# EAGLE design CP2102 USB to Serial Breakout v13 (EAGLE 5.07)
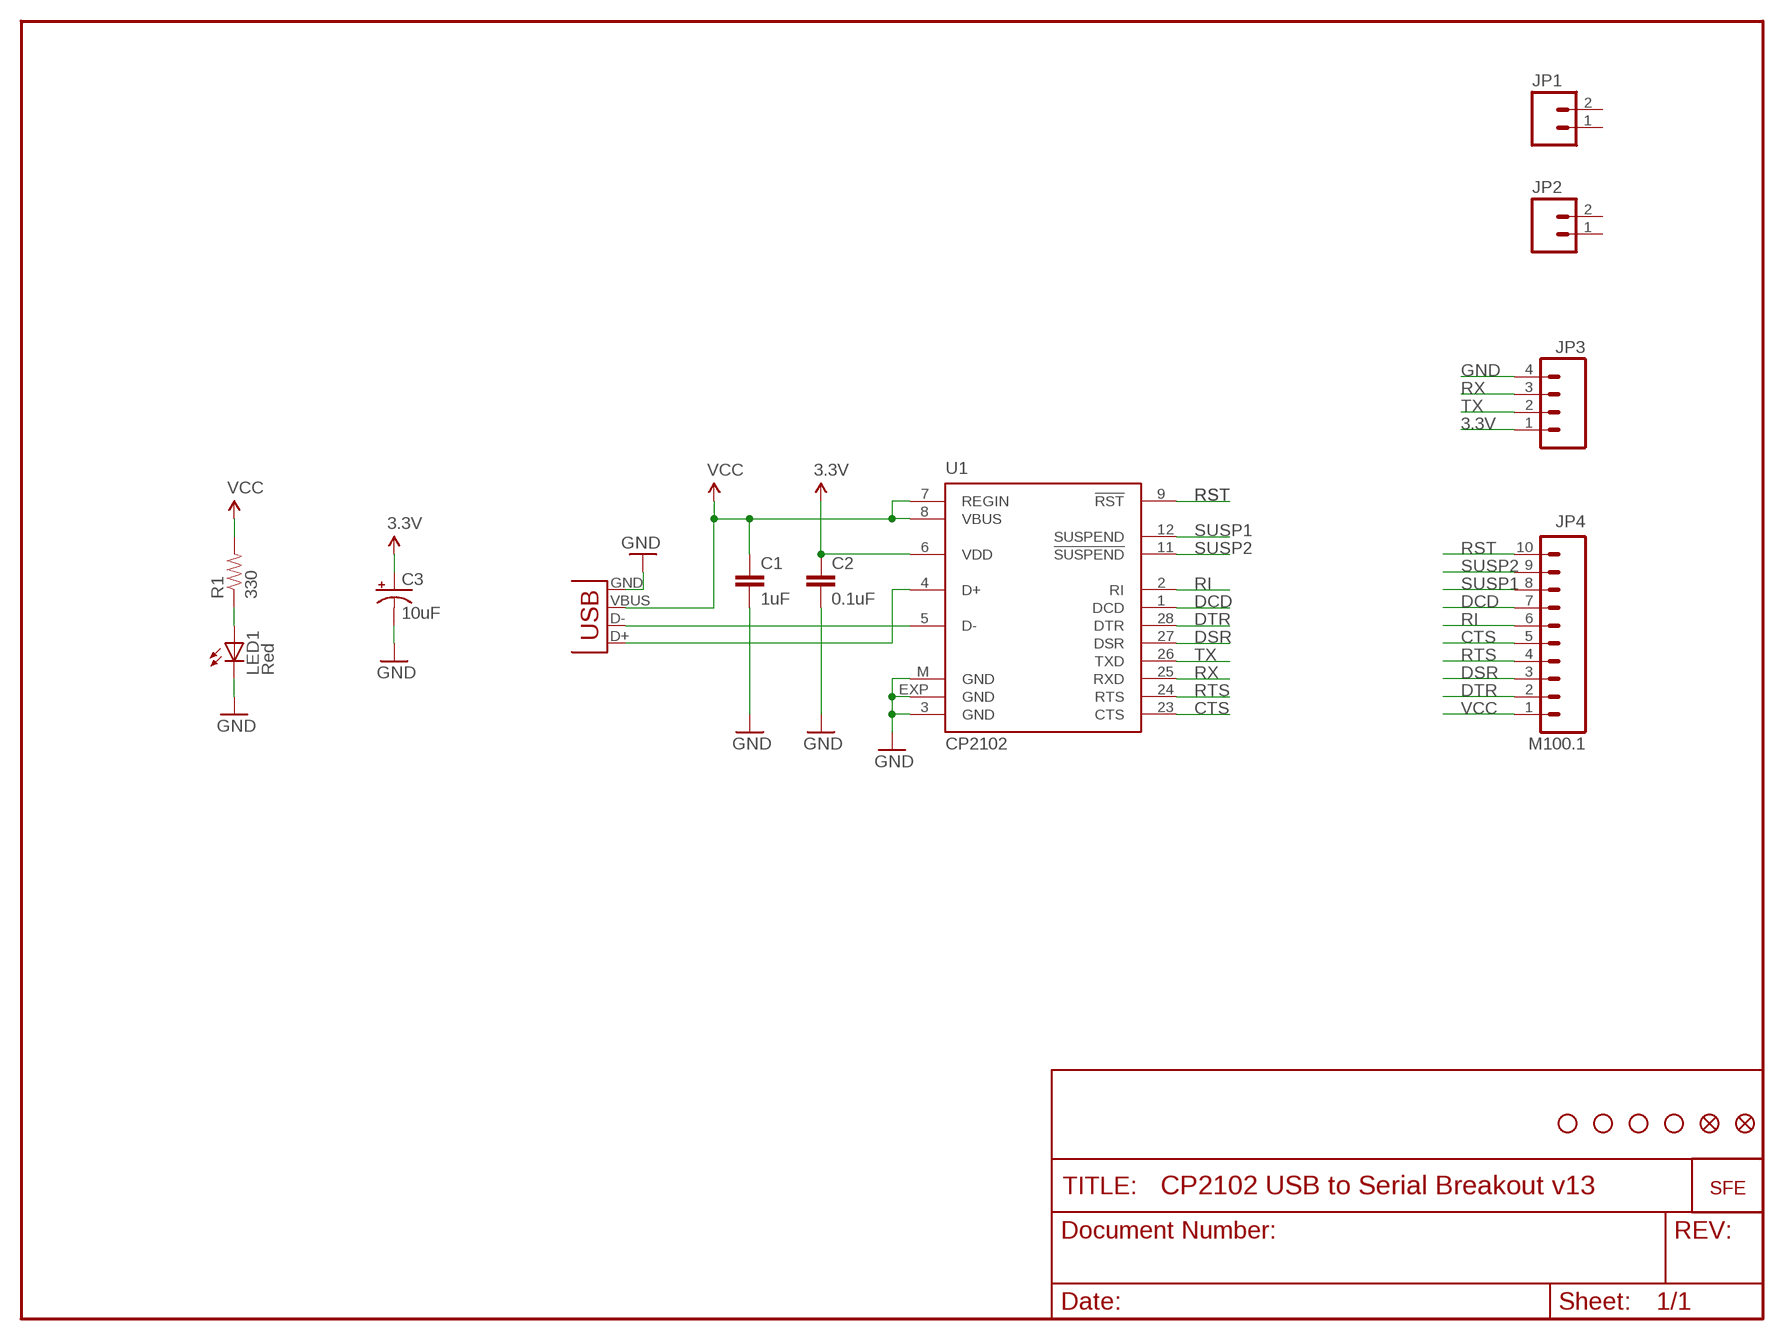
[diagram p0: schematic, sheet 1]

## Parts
C1  1uF  CAP0603-CAP  [0603-CAP]
C2  0.1uF  CAP0603-CAP  [0603-CAP]
C3  10uF  CAP_POL1206  [EIA3216]
JP1  M02PTH  [1X02]
JP2  M02PTH  [1X02]
JP3  M04PTH  [1X04]
JP4  M100.1  M10"  [1X10]
LED1  Red  LED1206  [LED-1206]
R1  330  RESISTOR0603-RES  [0603-RES]
U1  CP2102  CP210X_USB_UART  [MLP28]
U$1  LOGO-SFENEW  [SFE-NEW-WEBLOGO]
U$2  FIDUCIAL1X2  [FIDUCIAL-1X2]
U$3  FIDUCIAL1X2  [FIDUCIAL-1X2]
U$6  STAND-OFF  [STAND-OFF]
U$7  STAND-OFF  [STAND-OFF]
U$8  STAND-OFF  [STAND-OFF]
U$9  STAND-OFF  [STAND-OFF]
X1  USBPTH  [USB-B-PTH]

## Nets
3.3V: C2.1 C3.A(+) JP3.1 U1.6(VDD)
CTS: JP4.5 U1.23(CTS)
DCD: JP4.7 U1.1(DCD)
DSR: JP4.3 U1.27(DSR)
DTR: JP4.2 U1.28(DTR)
GND: C1.2 C2.2 C3.C(-) JP3.4 LED1.C U1.3(GND) U1.EXP(GND) U1.M(GND) X1.GND
N$1: U1.5(D-) X1.D-
N$2: U1.4(D+) X1.D+
N$3: LED1.A R1.1
RI: JP4.6 U1.2(RI)
RST: JP4.10 U1.9(!RST)
RTS: JP4.4 U1.24(RTS)
RX: JP3.3 U1.25(RXD)
SUSP1: JP4.8 U1.12(SUSPEND)
SUSP2: JP4.9 U1.11(!SUSPEND)
TX: JP3.2 U1.26(TXD)
VCC: C1.1 JP4.1 R1.2 U1.7(REGIN) U1.8(VBUS) X1.VBUS
Unconnected: JP1.1 JP1.2 JP2.1 JP2.2

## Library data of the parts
C1 C2 = SparkFun:CAP: Capacitor
C3 = SparkFun:CAP_POL: Capacitor Polarized
JP1 JP2 = SparkFun:M02: Header 2
JP3 = SparkFun:M04: Header 4 Standard 4-pin 0.1" header. Use with straight break away headers (SKU : PRT-00116), right angle break away headers (PRT-00553), swiss pins (PRT-00743), machine pins (PRT-00117), and female headers (PRT-00115). Molex polarized connector foot print use with SKU : PRT-08231 with associated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
JP4 = SparkFun:M10: Header 10 Standard 10-pin 0.1" header. Use with straight break away headers (SKU : PRT-00116), right angle break away headers (PRT-00553), swiss pins (PRT-00743), machine pins (PRT-00117), and female headers (PRT-00115).
LED1 = SparkFun:LED: LEDs
R1 = SparkFun:RESISTOR: Resistor
U1 = SparkFun:CP210X_USB_UART: Single-Chip USB to UART Bridge Source: www.silabs.com .. CP2101.pdf / cp2102.pdf. Spark Fun Electronics SKU : COM-00310
U$1 = SparkFun:LOGO-SFE: Spark Fun Electronics PCB Logo
U$2 U$3 = SparkFun:FIDUCIAL: Fiducial Alignment Points
U$6-U$9 = SparkFun:STAND-OFF: Stand Off
X1 = SparkFun:USB: USB Connectors USB-B-PTH is fully proven SKU : PRT-00139 USB-miniB is fully proven SKU : PRT-00587 USB-A-PCB is untested. USB-A-H is throughly reviewed, but untested. Spark Fun Electronics SKU : PRT-00437 USB-B-SMT is throughly reviewed, but untested. Needs silkscreen touching up. USB-A-S has not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

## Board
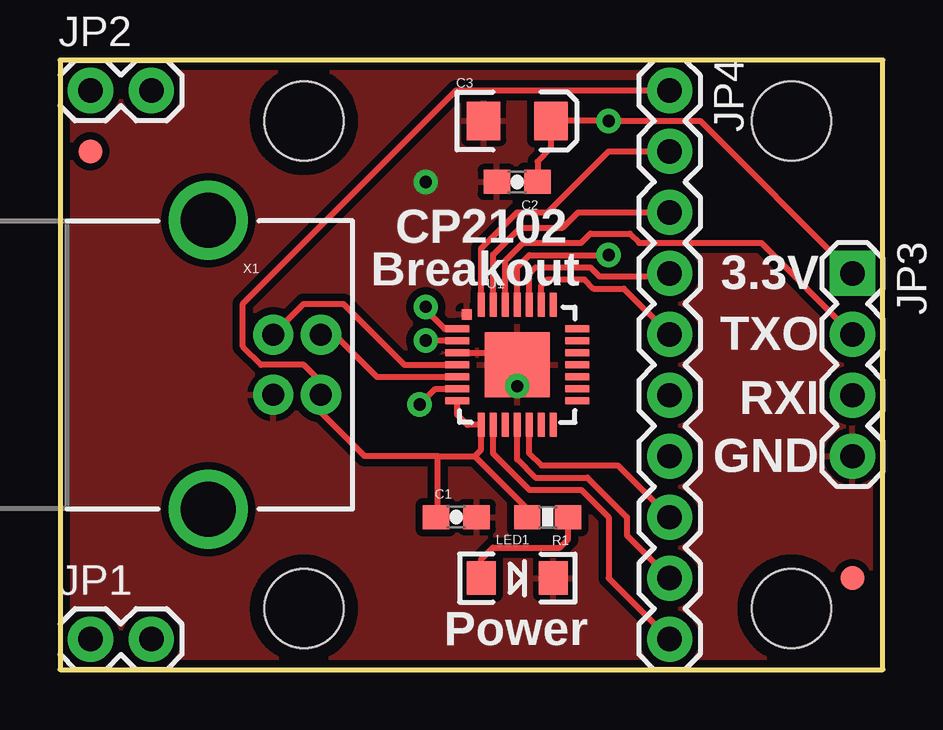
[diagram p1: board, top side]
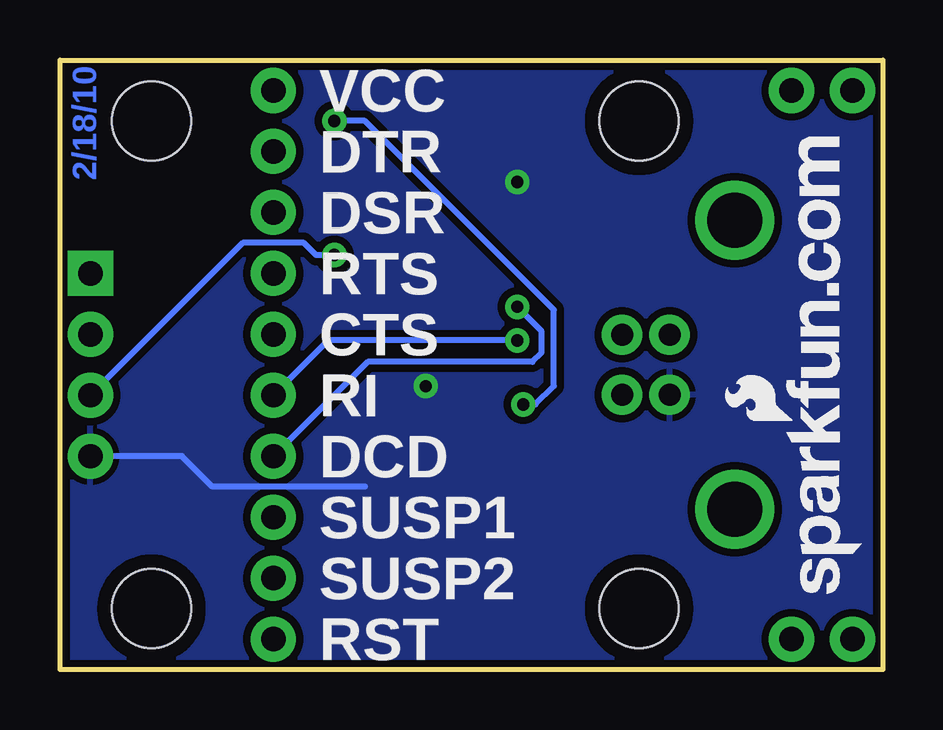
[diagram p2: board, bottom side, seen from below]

Size 34.29 x 25.4 mm. Coordinates in mm from the lower left corner, seen from the top.
Outline: 0,0 34.29,0 34.29,25.4 0,25.4 0,0
Copper layers (1*16): Top 0.035mm / dielectric 1.5mm / Bottom 0.035mm
Design rules "SparkFun": minimum track width 8mil, minimum drill 20mil, track to track 8mil, track to pad 8mil, pad to pad 8mil, via to via 8mil, smd to smd 8mil, copper to edge 8mil, drill to drill 8mil, minimum pad ring 12mil, minimum via ring 10mil, stop-mask expansion 4mil, vias tented up to drill 20mil, thermal gap 10mil

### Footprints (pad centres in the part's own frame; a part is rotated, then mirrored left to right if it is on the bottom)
0603-CAP = smd 1.1 x 1: 1 -0.85,0; 2 0.85,0
EIA3216 = smd 1.4 x 1.6: A 1.4,0; C -1.4,0
1X02 = drill 1.016 pad 1.88 round: 1 0,0; 2 2.54,0
1X04 = drill 1.016 pad 1.88 square: 1 0,0 | drill 1.016 pad 1.88 round: 2 2.54,0; 3 5.08,0; 4 7.62,0
1X10 = drill 1.016 pad 1.88 round: 1 0,0; 2 2.54,0; 3 5.08,0; 4 7.62,0; 5 10.16,0; 6 12.7,0; 7 15.24,0; 8 17.78,0; 9 20.32,0; 10 22.86,0
LED-1206 = smd 1.2 x 1.4: A -1.5,0; C 1.5,0
0603-RES = smd 1.1 x 1: 1 -0.85,0; 2 0.85,0
MLP28 = smd 1 x 0.3: 1 -2.5,1.5; 2 -2.5,1; 3 -2.5,0.5; 4 -2.5,0; 5 -2.5,-0.5; 6 -2.5,-1; 7 -2.5,-1.5; 15 2.5,-1.5; 16 2.5,-1; 17 2.5,-0.5; 18 2.5,0; 19 2.5,0.5; 20 2.5,1; 21 2.5,1.5 | smd 0.3 x 1: 8 -1.5,-2.5; 9 -1,-2.5; 10 -0.5,-2.5; 11 0,-2.5; 12 0.5,-2.5; 13 1,-2.5; 14 1.5,-2.5; 22 1.5,2.5; 23 1,2.5; 24 0.5,2.5; 25 0,2.5; 26 -0.5,2.5; 27 -1,2.5; 28 -1.5,2.5 | smd 2.7 x 2.7: EXP 0,0 | smd 0.435 x 0.435: M -2.103,2.103
FIDUCIAL-1X2 = smd 1 x 1: 1 0,0
STAND-OFF = hole 3.302: 0,0
USB-B-PTH = drill 0.914 pad 1.676 round: D+ 0,1.25; D- 1.981,1.25; GND 0,-1.25; VBUS 1.981,-1.25 | drill 2.286 round: P$1 -2.718,-6.02; P$2 -2.718,6.02

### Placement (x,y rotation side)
C1  16.51,6.35 0 top
C2  19.05,20.32 180 top
C3  19.05,22.86 0 top
JP1  1.27,1.27 0 top
JP2  1.27,24.13 0 top
JP3  33.02,16.51 270 top
JP4  25.4,24.13 270 top
LED1  19.05,3.81 0 top
R1  20.32,6.35 180 top
U1  19.05,12.7 0 top
U$1  0.89,3.17 90 bottom
U$2  33.02,3.81 0 top
U$3  1.27,21.59 0 top
U$6  10.16,2.54 0 top
U$7  10.16,22.86 0 top
U$8  30.48,22.86 0 top
U$9  30.48,2.54 0 top
X1  8.89,12.7 0 top

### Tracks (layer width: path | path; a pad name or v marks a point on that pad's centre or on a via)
3.3V  (via drill 0.51)
  Top 0.254: U1.6 15.64,11.7 v14.99,11.05 | JP3.1 26.67,22.86 v22.86,22.86 C3.A 20.45,21.72 19.9,21.17 C2.1
  Bottom 0.254: v14.99,11.05 14.48,11.05 13.72,11.81 13.72,14.99 21.59,22.86 v22.86,22.86
CTS
  Top 0.254: U1.23 20.05,15.99 20.32,16.26 21.84,16.26 22.23,15.88 23.5,15.88 JP4.5
DCD  (via drill 0.51)
  Top 0.254: v15.24,15.11 15.24,14.99 16.03,14.2 U1.1
  Bottom 0.254: v15.24,15.11 14.22,14.1 14.22,13.21 14.61,12.83 21.46,12.83 JP4.7
DSR
  Top 0.254: U1.27 18.05,17.29 19.18,18.41 20.95,18.41 21.59,19.05 JP4.3
DTR
  Top 0.254: U1.28 17.55,17.55 19.05,19.05 20.32,19.05 22.86,21.59 JP4.2
GND  (via drill 0.51)
  Top 0.254: U1.3 18.55,13.2 U1.EXP
  Bottom 0.254: JP3.4 29.21,8.89 27.94,7.62 21.59,7.62
  other vias: 15.24,20.32 19.05,11.81
  pour Bottom (isolate 0.305): 0,0 0,25.4 34.29,25.4 34.29,0
  pour Top (isolate 0.305): 0,0 0,25.4 34.29,25.4 34.29,0
N$1
  Top 0.254: X1.D- 11.45,13.95 13.2,12.2 U1.5
N$2
  Top 0.254: U1.4 14.35,12.7 11.81,15.24 10.16,15.24 8.89,13.97 X1.D+
N$3
  Top 0.254: R1.1 21.17,5.42 20.83,5.08 18.03,5.08 17.55,4.6 LED1.A
RI  (via drill 0.51)
  Top 0.254: U1.2 15.26,13.7 v15.24,13.72
  Bottom 0.254: v15.24,13.72 23.11,13.72 JP4.6
RST
  Top 0.254: U1.9 18.05,9 19.56,7.49 21.72,7.49 22.86,6.35 22.86,3.81 JP4.10
RTS
  Top 0.254: U1.24 19.55,16.5 19.81,16.76 22.1,16.76 22.48,16.38 25.27,16.38 JP4.4
RX  (via drill 0.51)
  Top 0.254: U1.25 19.05,16.76 19.56,17.27 v22.86,17.27
  Bottom 0.254: v22.86,17.27 23.62,17.27 24.13,17.78 26.67,17.78 JP3.3
SUSP1
  Top 0.254: U1.12 19.55,9.03 20.07,8.51 23.24,8.51 JP4.8
SUSP2
  Top 0.254: U1.11 19.05,8.76 19.81,8 21.97,8 23.62,6.35 23.62,5.59 JP4.9
TX
  Top 0.254: U1.26 18.55,17.03 19.3,17.78 21.72,17.78 22.1,18.16 23.75,18.16 24.13,17.78 29.21,17.78 JP3.2
VCC
  Top 0.254: JP4.1 16.51,24.13 7.62,15.24 7.62,13.46 8.38,12.7 10.16,12.7 10.87,11.99 X1.VBUS 10.87,10.72 12.7,8.89 15.75,8.89 | 17.27,8.89 17.55,9.17 U1.8 16.98,10.2 16.55,10.63 U1.7 | 15.75,8.89 17.27,8.89 | 15.75,8.89 15.75,6.35 C1.1 | R1.2 19.47,6.69 17.27,8.89

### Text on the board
Bottom: 2/18/10
tPlace: CP2102 | 3.3V | Breakout | TXO | RXI | GND | Power
bPlace: VCC | DTR | DSR | RTS | CTS | RI | DCD | SUSP1 | SUSP2 | RST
